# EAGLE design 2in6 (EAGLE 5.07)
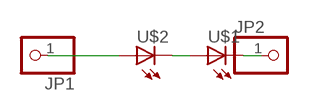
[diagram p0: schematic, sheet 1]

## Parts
JP1  PINHD-1X11X0.4  [1X01]
JP2  PINHD-1X11X0.4  [1X01]
U$1  LEDSMT1206  [1206]
U$2  LEDSMT1206  [1206]

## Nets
N$1: JP1.1 U$2.A
N$3: U$1.A U$2.C
N$4: JP2.1 U$1.C

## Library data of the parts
JP1 JP2 = pinhead:PINHD-1X1: PIN HEADER
U$1 U$2 = led(2):LED: LED

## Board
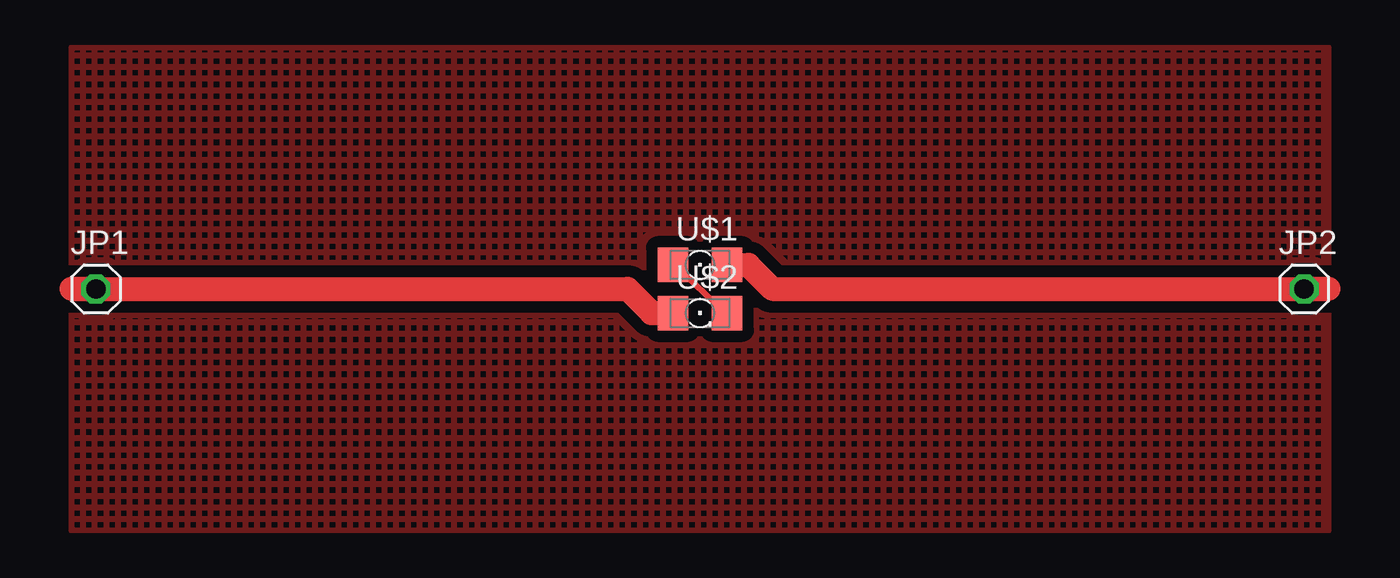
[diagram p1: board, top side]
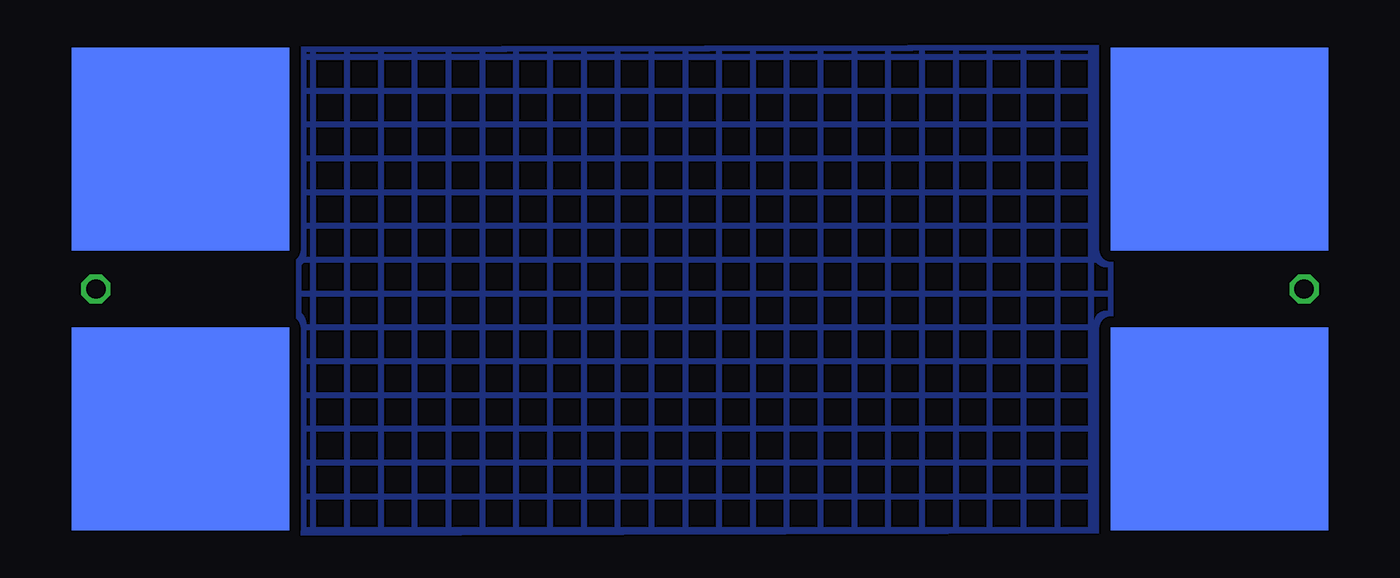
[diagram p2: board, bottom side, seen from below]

No outline drawn. Coordinates in mm, seen from the top.
Copper layers (1*16): Top 0.035mm / dielectric 1.5mm / Bottom 0.035mm
Design rules "default": minimum track width 10mil, minimum drill 24mil, track to track 8mil, track to pad 8mil, pad to pad 8mil, via to via 8mil, smd to smd 8mil, copper to edge 40mil, drill to drill 8mil, minimum pad ring 10mil, minimum via ring 8mil, stop-mask expansion 4mil, vias tented up to drill 0mil, thermal gap 10mil

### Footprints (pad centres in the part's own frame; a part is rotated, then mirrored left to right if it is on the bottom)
1X01 = drill 1.016 octagon: 1 0,0
1206 = smd 1.6 x 1.803: A -1.422,0; C 1.422,0

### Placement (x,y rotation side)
JP1  1.27,12.7 0 top
JP2  64.77,12.7 0 top
U$1  33.02,13.97 0 top
U$2  33.02,11.43 0 top

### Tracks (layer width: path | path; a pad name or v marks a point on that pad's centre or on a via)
N$1
  Top 1.27: JP1.1 0,12.7 29.21,12.7 30.48,11.43 U$2.A
N$2
  pour Top (isolate 0.61, hatched): 0,25.4 66.04,25.4 66.04,0 0,0
  pour Bottom (isolate 0.61, hatched): 11.43,25.4 54.1,25.27 54.1,-0.13 11.43,0
N$3
  Top 0.305: U$2.C 34.29,11.43 31.75,13.97 U$1.A
N$4
  Top 1.27: JP2.1 66.04,12.7 36.83,12.7 35.56,13.97 U$1.C
(copper drawn outside any net)
  shapes: Bottom area x4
